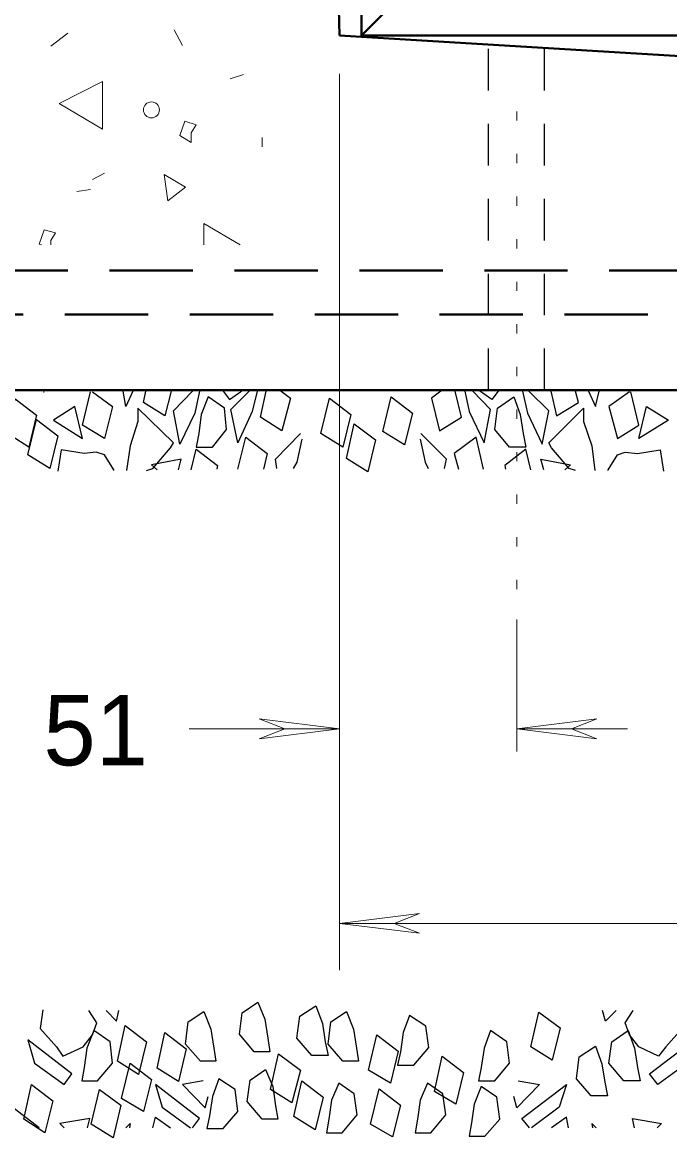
# Model space of a CAD drawing. Extents: x 312583 to 312854, y 144419 to 144597.
# Drawn here: x 312643.91 to 312650.91, y 144443.01 to 144455.06 of the extents above; entities that cross this region are included whole.
import ezdxf

# ---------------------------------------------------------------- set-up
doc = ezdxf.new("R2010")
doc.units = 0
doc.header["$LTSCALE"] = 0.3
for name, pattern in [('DOTTED', [1.5, 0.3, -1.2]), ('MEDIUM_DASHED', [4.5, 3, -1.5]), ('SHORT_DASHED', [2.7, 1.5, -1.2])]:
    doc.linetypes.add(name, pattern=pattern)
doc.layers.add('1', color=7, linetype='Continuous', lineweight=25)
doc.layers.add('2', color=7, linetype='Continuous', lineweight=13)

msp = doc.modelspace()

# ---------------------------------------------------------------- linework, layer by layer
at = {"layer": '1', "lineweight": 40}
for p, q in [((312646.6198, 144493.0154), (312647.3405, 144454.9198)), ((312647.5781, 144461.6281), (312647.5781, 144454.9198)), ((312648.5365, 144455.8781), (312647.5781, 144454.9198)), ((312655.2448, 144454.4368), (312647.3405, 144454.9198)), ((312647.5781, 144454.9198), (312662.9115, 144454.9198)), ((312626.2571, 144451.0864), (312669.6198, 144451.0864))]:
    msp.add_line(p, q, dxfattribs=at)
at = {"layer": '1', "lineweight": 13}
for p, q in [((312644.4041, 144454.9428), (312644.2201, 144454.8048)), ((312645.5541, 144454.9811), (312645.6461, 144454.8124)), ((312646.1598, 144454.4521), (312646.3055, 144454.4981)), ((312646.5048, 144453.7161), (312646.5048, 144453.8158)), ((312644.6725, 144453.3634), (312644.8028, 144453.4324)), ((312644.5038, 144453.2331), (312644.6495, 144453.2561)), ((312645.8761, 144452.8881), (312645.8761, 144452.6581)), ((312646.2671, 144452.6581), (312645.8761, 144452.8881)), ((312644.2201, 144452.6581), (312644.2201, 144452.7041))]:
    msp.add_line(p, q, dxfattribs=at)
at = {"layer": '1', "linetype": 'SHORT_DASHED'}
for p, q in [((312648.9505, 144451.0864), (312648.9505, 144454.8431)), ((312649.5561, 144451.0864), (312649.5561, 144454.8048))]:
    msp.add_line(p, q, dxfattribs=at)
at = {"layer": '1', "linetype": 'MEDIUM_DASHED', "lineweight": 40}
for p, q in [((312643.5071, 144452.3821), (312667.7031, 144452.3821)), ((312628.1738, 144451.9068), (312667.4655, 144451.9068))]:
    msp.add_line(p, q, dxfattribs=at)
at = {"layer": '1'}
for p, q in [((312644.1435, 144451.0711), (312644.1511, 144451.0711)), ((312644.5651, 144450.7108), (312644.6495, 144451.0711)), ((312645.2245, 144450.9561), (312645.2475, 144451.0788)), ((312645.5465, 144450.8641), (312645.7535, 144451.0788)), ((312646.1675, 144450.8794), (312646.3668, 144451.0788)), ((312646.4895, 144450.7951), (312646.5508, 144451.0788)), ((312648.6591, 144450.7951), (312648.5901, 144451.0788)), ((312648.9735, 144450.8794), (312648.7818, 144451.0788)), ((312649.6021, 144450.8641), (312649.3875, 144451.0788)), ((312649.9241, 144450.9561), (312649.8935, 144451.0788)), ((312650.5758, 144450.7108), (312650.4915, 144451.0711)), ((312646.6505, 144450.3428), (312646.9188, 144450.6188)), ((312648.4981, 144450.3428), (312648.2221, 144450.6188)), ((312646.6658, 144450.2431), (312646.6505, 144450.3428)), ((312648.4751, 144450.2431), (312648.4981, 144450.3428)), ((312645.3088, 144450.2814), (312645.3701, 144450.2278)), ((312649.8398, 144450.2814), (312649.7785, 144450.2278)), ((312645.8685, 144443.6268), (312645.6461, 144443.5884)), ((312649.2725, 144443.6268), (312649.5025, 144443.5884)), ((312645.4238, 144443.3431), (312645.7305, 144443.1208)), ((312649.7171, 144443.3431), (312649.4181, 144443.1208)), ((312644.3198, 144443.1668), (312644.3658, 144443.1208)), ((312650.8211, 144443.1668), (312650.7751, 144443.1208))]:
    msp.add_line(p, q, dxfattribs=at)
at = {"layer": '1', "lineweight": 13}
for points in [[(312644.7798, 144453.9078), (312644.7798, 144454.4214), (312644.3121, 144454.1838)], [(312645.7381, 144453.8694), (312645.7918, 144453.9538), (312645.6691, 144453.9921), (312645.6155, 144453.8388), (312645.7381, 144453.7621)], [(312645.4851, 144453.1334), (312645.6768, 144453.2791), (312645.4468, 144453.4171)]]:
    msp.add_lwpolyline(points, close=True, dxfattribs=at)
msp.add_lwpolyline([(312644.2201, 144452.7041), (312644.2738, 144452.7884), (312644.1511, 144452.8191), (312644.0975, 144452.6658), (312644.1205, 144452.6581)], dxfattribs=at)
at = {"layer": '1'}
for points in [[(312644.6725, 144451.0711), (312644.8871, 144450.9101), (312644.8028, 144450.5651), (312644.5651, 144450.7108)], [(312645.1095, 144451.0788), (312645.0328, 144450.9101), (312645.0021, 144451.0788)], [(312645.5235, 144451.0788), (312645.4545, 144450.8104), (312645.2245, 144450.9561)], [(312645.8301, 144451.0788), (312645.7765, 144450.8411), (312645.6155, 144450.5038), (312645.5465, 144450.8641)], [(312646.0831, 144451.0788), (312646.1521, 144450.9868), (312646.2518, 144451.0558), (312646.2825, 144451.0788)], [(312646.4511, 144451.0788), (312646.3975, 144450.8564), (312646.2441, 144450.5191), (312646.1675, 144450.8794)], [(312646.6965, 144451.0864), (312646.8115, 144451.0021), (312646.7195, 144450.6494), (312646.4895, 144450.7951)], [(312648.4521, 144451.0864), (312648.3371, 144451.0021), (312648.4215, 144450.6494), (312648.6591, 144450.7951)], [(312648.6975, 144451.0788), (312648.7435, 144450.8564), (312648.9045, 144450.5191), (312648.9735, 144450.8794)], [(312649.0578, 144451.0788), (312648.9888, 144450.9868), (312648.8891, 144451.0558), (312648.8585, 144451.0788)], [(312649.3185, 144451.0788), (312649.3721, 144450.8411), (312649.5331, 144450.5038), (312649.6021, 144450.8641)], [(312649.6251, 144451.0788), (312649.6865, 144450.8104), (312649.9241, 144450.9561)], [(312650.0315, 144451.0788), (312650.1081, 144450.9101), (312650.1465, 144451.0788)], [(312650.4761, 144451.0711), (312650.2538, 144450.9101), (312650.3458, 144450.5651), (312650.5758, 144450.7108)], [(312645.2551, 144450.2201), (312645.3241, 144450.2431), (312645.5158, 144450.4654), (312645.5465, 144450.5191), (312645.1631, 144450.8948), (312645.1631, 144450.7491)], [(312649.8935, 144450.2201), (312649.8245, 144450.2431), (312649.6328, 144450.4654), (312649.6021, 144450.5191), (312649.9778, 144450.8948), (312649.9778, 144450.7491)], [(312645.1631, 144450.7491), (312645.0788, 144450.4884), (312645.0405, 144450.2201)], [(312649.9778, 144450.7491), (312650.0698, 144450.4884), (312650.1005, 144450.2201)], [(312646.2441, 144450.2354), (312646.3285, 144450.5804), (312646.5585, 144450.4041), (312646.5201, 144450.2354)], [(312648.8968, 144450.2354), (312648.8201, 144450.5804), (312648.5825, 144450.4041), (312648.6285, 144450.2354)], [(312645.7381, 144450.2278), (312645.7918, 144450.4501), (312646.0218, 144450.2738), (312646.0141, 144450.2354)], [(312646.9341, 144450.5574), (312646.8805, 144450.3121), (312646.8421, 144450.2431)], [(312648.2145, 144450.5574), (312648.2681, 144450.3121), (312648.2988, 144450.2431)], [(312649.4105, 144450.2278), (312649.3568, 144450.4501), (312649.1268, 144450.2738), (312649.1345, 144450.2354)], [(312644.9025, 144450.2201), (312644.9025, 144450.2278), (312644.8028, 144450.3888), (312644.7108, 144450.4194), (312644.5805, 144450.4041), (312644.3351, 144450.4424), (312644.2968, 144450.2124)], [(312645.6001, 144450.2278), (312645.6308, 144450.3428), (312645.3088, 144450.2814)], [(312649.5485, 144450.2278), (312649.5178, 144450.3428), (312649.8398, 144450.2814)], [(312650.2461, 144450.2201), (312650.2461, 144450.2278), (312650.3458, 144450.3888), (312650.4301, 144450.4194), (312650.5605, 144450.4041), (312650.8058, 144450.4424), (312650.8441, 144450.2124)], [(312644.1358, 144444.3934), (312644.1051, 144444.1941), (312644.2815, 144443.9948)], [(312644.2815, 144443.9948), (312644.3505, 144443.8951), (312644.5728, 144443.9948), (312644.6725, 144444.1251), (312644.7185, 144444.2554), (312644.6341, 144444.3858)], [(312644.8181, 144444.3858), (312644.9331, 144444.2708), (312644.9561, 144444.3858)], [(312650.3305, 144444.3858), (312650.2155, 144444.2708), (312650.1848, 144444.3858)], [(312650.8671, 144443.9948), (312650.7905, 144443.8951), (312650.5758, 144443.9948), (312650.4761, 144444.1251), (312650.4301, 144444.2554), (312650.5145, 144444.3858)], [(312651.0128, 144444.3934), (312651.0435, 144444.1941), (312650.8671, 144443.9948)], [(312645.7535, 144443.1208), (312645.8301, 144443.2204), (312645.3548, 144443.5884), (312645.4238, 144443.3431)], [(312645.6461, 144443.5884), (312645.8915, 144443.3354), (312645.9221, 144443.4581)], [(312649.5025, 144443.5884), (312649.2571, 144443.3354), (312649.2265, 144443.4581)], [(312649.3951, 144443.1208), (312649.3108, 144443.2204), (312649.7938, 144443.5884), (312649.7171, 144443.3431)], [(312644.0975, 144443.1208), (312643.6528, 144443.4581), (312643.7295, 144443.2051)], [(312644.6188, 144443.1208), (312644.6418, 144443.2204), (312644.3198, 144443.1668)], [(312645.3241, 144443.1208), (312645.3548, 144443.2358), (312645.5158, 144443.1208)], [(312649.8168, 144443.1208), (312649.7938, 144443.2358), (312649.6328, 144443.1208)], [(312650.5298, 144443.1208), (312650.5068, 144443.2204), (312650.8211, 144443.1668)], [(312645.0328, 144443.1208), (312645.0788, 144443.1668), (312645.0711, 144443.1208)], [(312650.1158, 144443.1208), (312650.0698, 144443.1668), (312650.0775, 144443.1208)]]:
    msp.add_lwpolyline(points, dxfattribs=at)
for points in [[(312643.7525, 144450.6188), (312643.8368, 144450.9944), (312644.0668, 144450.8181), (312643.9825, 144450.4731)], [(312645.9221, 144451.0174), (312645.8455, 144450.8258), (312645.8225, 144450.6188), (312645.7918, 144450.4731), (312645.9681, 144450.4731), (312646.1215, 144450.6648), (312646.0985, 144450.8948)], [(312647.1411, 144450.6188), (312647.2331, 144451.0021), (312647.4631, 144450.8258), (312647.3788, 144450.4731)], [(312647.8081, 144450.6418), (312647.9001, 144451.0174), (312648.1301, 144450.8411), (312648.0458, 144450.4961)], [(312649.2265, 144451.0174), (312649.2955, 144450.8258), (312649.3261, 144450.6188), (312649.3568, 144450.4731), (312649.1805, 144450.4731), (312649.0195, 144450.6648), (312649.0501, 144450.8948)], [(312644.2508, 144450.7644), (312644.5651, 144450.5651), (312644.4808, 144450.9101)], [(312650.8978, 144450.7644), (312650.5758, 144450.5651), (312650.6601, 144450.9101)], [(312643.9748, 144450.3888), (312644.0668, 144450.7721), (312644.2968, 144450.5958), (312644.2125, 144450.2431)], [(312647.4171, 144450.3504), (312647.5015, 144450.7261), (312647.7315, 144450.5498), (312647.6471, 144450.2048)], [(312646.4588, 144444.4778), (312646.5355, 144444.2938), (312646.5661, 144444.0868), (312646.5891, 144443.9411), (312646.4205, 144443.9411), (312646.2595, 144444.1328), (312646.2901, 144444.3628)], [(312647.0875, 144444.4394), (312647.1565, 144444.2478), (312647.1871, 144444.0484), (312647.2178, 144443.9028), (312647.0415, 144443.9028), (312646.8805, 144444.0868), (312646.9111, 144444.3244)], [(312645.8761, 144444.3781), (312645.9528, 144444.1864), (312645.9835, 144443.9794), (312646.0065, 144443.8414), (312645.8378, 144443.8414), (312645.6768, 144444.0254), (312645.7075, 144444.2631)], [(312647.4171, 144444.3781), (312647.4938, 144444.1864), (312647.5245, 144443.9794), (312647.5475, 144443.8414), (312647.3788, 144443.8414), (312647.2178, 144444.0254), (312647.2485, 144444.2631)], [(312648.0995, 144444.3321), (312648.0305, 144444.1481), (312647.9998, 144443.9411), (312647.9691, 144443.7954), (312648.1455, 144443.7954), (312648.3065, 144443.9871), (312648.2758, 144444.2171)], [(312649.4105, 144443.9948), (312649.4948, 144444.3704), (312649.7248, 144444.2018), (312649.6405, 144443.8491)], [(312644.9408, 144443.8414), (312645.0251, 144444.2248), (312645.2551, 144444.0484), (312645.1708, 144443.6958)], [(312644.0438, 144443.8184), (312644.3658, 144443.5884), (312644.4501, 144443.7034), (312643.9748, 144444.0714)], [(312644.6878, 144444.1711), (312644.6111, 144443.9794), (312644.5805, 144443.7724), (312644.5575, 144443.6268), (312644.7261, 144443.6268), (312644.8871, 144443.8184), (312644.8641, 144444.0484)], [(312645.3701, 144443.7648), (312645.4545, 144444.1481), (312645.6845, 144443.9718), (312645.6001, 144443.6191)], [(312647.6548, 144443.7418), (312647.7468, 144444.1251), (312647.9768, 144443.9488), (312647.8925, 144443.6038)], [(312648.9735, 144444.1711), (312648.9045, 144443.9794), (312648.8738, 144443.7724), (312648.8431, 144443.6268), (312649.0195, 144443.6268), (312649.1805, 144443.8184), (312649.1498, 144444.0484)], [(312650.4608, 144444.1711), (312650.5298, 144443.9794), (312650.5605, 144443.7724), (312650.5911, 144443.6268), (312650.4148, 144443.6268), (312650.2538, 144443.8184), (312650.2845, 144444.0484)], [(312651.0971, 144443.8184), (312650.7828, 144443.5884), (312650.6908, 144443.7034), (312651.1738, 144444.0714)], [(312650.1081, 144444.0024), (312650.1771, 144443.8108), (312650.2078, 144443.6114), (312650.2385, 144443.4658), (312650.0621, 144443.4658), (312649.9011, 144443.6498), (312649.9318, 144443.8874)], [(312646.5968, 144443.5348), (312646.6811, 144443.9181), (312646.9188, 144443.7418), (312646.8268, 144443.3891)], [(312648.3678, 144443.5118), (312648.4521, 144443.8951), (312648.6821, 144443.7188), (312648.5978, 144443.3738)], [(312644.9868, 144443.4351), (312645.0788, 144443.8184), (312645.3088, 144443.6421), (312645.2245, 144443.2971)], [(312646.5431, 144443.7494), (312646.6198, 144443.5654), (312646.6505, 144443.3584), (312646.6735, 144443.2128), (312646.5048, 144443.2128), (312646.3438, 144443.4044), (312646.3745, 144443.6344)], [(312643.9288, 144443.2128), (312644.0131, 144443.5884), (312644.2431, 144443.4121), (312644.1588, 144443.0671)], [(312646.0371, 144443.6498), (312645.9681, 144443.4581), (312645.9375, 144443.2511), (312645.9068, 144443.1131), (312646.0831, 144443.1131), (312646.2441, 144443.2971), (312646.2135, 144443.5348)], [(312646.8498, 144443.2434), (312646.9341, 144443.6268), (312647.1641, 144443.4504), (312647.0798, 144443.0978)], [(312647.3328, 144443.6038), (312647.2561, 144443.4198), (312647.2255, 144443.2128), (312647.2025, 144443.0671), (312647.3711, 144443.0671), (312647.5321, 144443.2588), (312647.5015, 144443.4888)], [(312648.2911, 144443.6038), (312648.2145, 144443.4198), (312648.1838, 144443.2128), (312648.1608, 144443.0671), (312648.3295, 144443.0671), (312648.4905, 144443.2588), (312648.4598, 144443.4888)], [(312644.6571, 144443.1591), (312644.7491, 144443.5348), (312644.9791, 144443.3661), (312644.8948, 144443.0134)], [(312647.6778, 144443.1591), (312647.7698, 144443.5424), (312647.9998, 144443.3661), (312647.9155, 144443.0211)], [(312648.8738, 144443.5654), (312648.7971, 144443.3738), (312648.7665, 144443.1744), (312648.7435, 144443.0288), (312648.9121, 144443.0288), (312649.0731, 144443.2128), (312649.0425, 144443.4504)]]:
    msp.add_lwpolyline(points, close=True, dxfattribs=at)
at = {"layer": '1', "lineweight": 13}
msp.add_circle((312645.3095, 144454.1159), 0.0865, dxfattribs=at)
at = {"layer": '2'}
for p, q in [((312647.3405, 144454.5058), (312647.3405, 144444.8228)), ((312649.2571, 144448.6101), (312649.2571, 144447.1841)), ((312646.4741, 144447.5368), (312646.7501, 144447.4294)), ((312647.3405, 144447.4294), (312646.4741, 144447.5368)), ((312649.2571, 144447.4294), (312650.1235, 144447.5368)), ((312650.1235, 144447.5368), (312649.8475, 144447.4294)), ((312647.3405, 144447.4294), (312645.7151, 144447.4294)), ((312646.4741, 144447.3221), (312646.7501, 144447.4294)), ((312647.3405, 144447.4294), (312646.4741, 144447.3221)), ((312650.4531, 144447.4294), (312649.2571, 144447.4294)), ((312649.2571, 144447.4294), (312650.1235, 144447.3221)), ((312650.1235, 144447.3221), (312649.8475, 144447.4294)), ((312647.3405, 144445.3288), (312648.2068, 144445.4361)), ((312648.2068, 144445.4361), (312647.9308, 144445.3288)), ((312647.3405, 144445.3288), (312663.1491, 144445.3288)), ((312647.3405, 144445.3288), (312648.2068, 144445.2214)), ((312648.2068, 144445.2214), (312647.9308, 144445.3288))]:
    msp.add_line(p, q, dxfattribs=at)
at = {"layer": '2', "linetype": 'DOTTED'}
msp.add_line((312649.2571, 144454.0994), (312649.2571, 144448.8248), dxfattribs=at)

# ---------------------------------------------------------------- texts
at = {"layer": '2'}
msp.add_text('51 ', height=0.76, dxfattribs=at).set_placement((312644.1415, 144447.0356))

doc.saveas('drawing.dxf')
